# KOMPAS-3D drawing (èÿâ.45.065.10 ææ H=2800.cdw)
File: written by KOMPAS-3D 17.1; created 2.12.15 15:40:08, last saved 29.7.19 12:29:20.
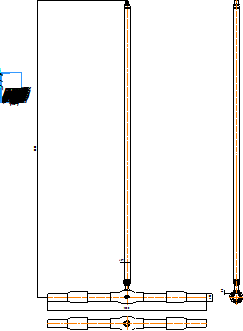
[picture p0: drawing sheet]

Sheet 1: A4, portrait

Title block, sheet 1: name: КШГ.45.065.10 С/С H=2800; mass: 39; sheets: 1; organisation: ООО "АДЛ Групп"; sheet format: A4; stored path: C:\Users\kka\KOMPAS_Work\Модели кранов для исследований\DN50\С удлинением\КШГ.32.050.40 СС ГЧ _ Шаровой кран БИВАЛ Ду50 Ру4 МПа редуцированный под приварку, с удлинением штока H=1100.cdw

Views: Вид 1, Проекционный вид 3
Referenced files in C:\Users\kka\KOMPAS_Work\Модели кранов для исследований\DN80\С удлинением\: КШТ.22.080.25 СС.a3d, КШГ.35.065.25 СС.a3d!КШГ.45.065.10 СС!Деталь (локальная).m3d
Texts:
  Klimkovich
  ADL
  Рама для чертежей
  Лит-Масса-Масштаб
  Материал-Предприятие
  Масштаб
  Изм.
  Лист
  № докум.
  Подп.
  Дата
  Лит.
  Разраб.
  Пров.
  Т.контр.
  Листов
  Внимание! Данный продукт является объектом авторского права ООО «Торговый Дом АДЛ».
  Запрещается изменение, копирование, распространение
  (в том числе путем копирования на другие сайты и ресурсы в Интернете)
  или любое иное использование информации и объектов без предварительного
  согласия правообладателя (ООО «Торговый Дом АДЛ»).
  Н.контр.
  Утв.
  ООО "Торговый дом АДЛ"
  Изменение
  Номер документа
  Подпись
  Обозначение документа
  Наименование изделия
  Масса изделия по ГОСТ 2.109-73
  Порядковый номер листа
  Общее количество листов в документе
  Характер работы, выполненной лицом, подписавшим документ
  Наименование или индекс предприятия, выпускающего документ
  Инв. № подл.
  Подп. и дата
  Взам. инв. №
  Инв. № дубл.
  Инвентарный номер подлинника по ГОСТ 2.501-68
  Подпись принявшего подлинник в отдел технической документации
  Инвентарный номер подлинника, взамен которого выпущен данный подлинник
  Инвентарный номер дубликата по ГОСТ 2.502-68
  Подпись принявшего дубликат в отдел технической документации
  Справ. №
  Перв. примен.
  Обозначение документа, взамен или на основании которого выпущен данный документ
  Обозначение документа, в котором впервые записан данный документ
  Подпись лица, копировавшего чертеж
  Обозначение формата листа
  !Рама для чертежа
Dimensions and other numbers on the sheet: 1500; 75; 57; 2800; 1:1; 1; 39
